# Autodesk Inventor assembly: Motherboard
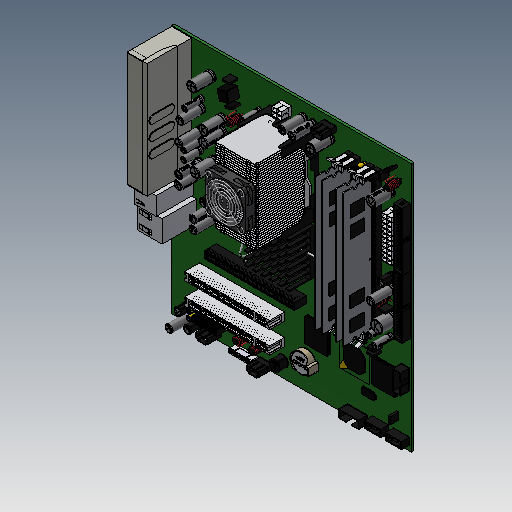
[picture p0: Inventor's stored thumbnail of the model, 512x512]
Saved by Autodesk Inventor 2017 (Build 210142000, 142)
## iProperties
Created: 2005-12
Part Number: Motherboard
Document SubType Name: Assembly
Designer: DanielSeverino
Author: DanielSeverino
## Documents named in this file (36)
- C:\Users\DanielSeverino\Desktop\01\Motherboard.iam
- C:\Users\DanielSeverino\Desktop\01\PCI Slot.ipt
- C:\Users\DanielSeverino\Desktop\01\Motherboard PCB.ipt
- C:\Users\DanielSeverino\Desktop\01\J9B1 Connector.ipt
- C:\Users\DanielSeverino\Desktop\01\J9C2 Connector.ipt
- C:\Users\DanielSeverino\Desktop\01\PCIE Connector.ipt
- C:\Users\DanielSeverino\Desktop\01\C9G5 connector.ipt
- C:\Users\DanielSeverino\Desktop\01\J9H2 Connector.ipt
- C:\Users\DanielSeverino\Desktop\01\IDE Male Connector.ipt
- C:\Users\DanielSeverino\Desktop\01\Power Supply Header 1.ipt
- C:\Users\DanielSeverino\Desktop\01\AGP slot.ipt
- C:\Users\DanielSeverino\Desktop\01\DDR Connector.ipt
- C:\Users\DanielSeverino\Desktop\01\Processor Heat Sink Mounting.ipt
- C:\Users\DanielSeverino\Desktop\01\Processor Heat Sink.ipt
- C:\Users\DanielSeverino\Desktop\01\RJ45 Module.ipt
- C:\Users\DanielSeverino\Desktop\01\USB Module.ipt
- C:\Users\DanielSeverino\Desktop\01\IO Interface Module.ipt
- C:\Users\DanielSeverino\Desktop\01\Capacitor 560 UF.ipt
- C:\Users\DanielSeverino\Desktop\01\Capacitor 1200 UF.ipt
- C:\Users\DanielSeverino\Desktop\01\Capacitor 640 UF.ipt
- C:\Users\DanielSeverino\Desktop\01\Capacitor 1000 UF.ipt
- C:\Users\DanielSeverino\Desktop\01\Capacitor 3000 UF.ipt
- C:\Users\DanielSeverino\Desktop\01\Choke.ipt
- C:\Users\DanielSeverino\Desktop\01\Battery.ipt
- C:\Users\DanielSeverino\Desktop\01\Bezel.ipt
- C:\Users\DanielSeverino\Desktop\01\Chip 15 x15.ipt
- C:\Users\DanielSeverino\Desktop\01\Capacitor 3500 UF.ipt
- C:\Users\DanielSeverino\Desktop\01\Chip block.ipt
- C:\Users\DanielSeverino\Desktop\01\Chip stand.ipt
- C:\Users\DanielSeverino\Desktop\01\Chip 13 x 6.ipt
- C:\Users\DanielSeverino\Desktop\01\Chip 22 x 11.ipt
- C:\Users\DanielSeverino\Desktop\01\Chip 24 x 23.ipt
- C:\Users\DanielSeverino\Desktop\01\RAM - DDR.ipt
- C:\Users\DanielSeverino\Desktop\01\Motherboard Heat Sink.ipt
- C:\Users\DanielSeverino\Desktop\01\Cooling Fan, 40mm x 40mm x 10 mm, 12VDC.iam
- C:\Users\DanielSeverino\Desktop\01\Power Supply Header 2.ipt
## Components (111 placed, 35 different names)
1. PCI Slot:3
2. Motherboard PCB:1
3. J9B1 Connector:1
4. J9B1 Connector:2
5. J9C2 Connector:1
6. PCIE Connector:1
7. C9G5 connector:1
8. J9H2 Connector:1
9. J9H2 Connector:2
10. C9G5 connector:2
11. IDE Male Connector:1
12. IDE Male Connector:2
13. Power Supply Header 1:1
14. J9B1 Connector:3
15. PCI Slot:1
16. PCI Slot:2
17. AGP slot:1
18. DDR Connector:1
19. DDR Connector:2
20. DDR Connector:3
21. DDR Connector:4
22. Processor Heat Sink Mounting:1
23. Processor Heat Sink:1
24. RJ45 Module:1
25. USB Module:1
26. IO Interface Module:1
27. Capacitor 560 UF:1
28. Capacitor 1200 UF:1
29. Capacitor 560 UF:2
30. Capacitor 640 UF:1
31. Capacitor 640 UF:2
32. Capacitor 1000 UF:2
33. Capacitor 3000 UF:1
34. Capacitor 1200 UF:2
35. Capacitor 560 UF:8
36. Capacitor 560 UF:9
37. Capacitor 560 UF:10
38. Capacitor 560 UF:11
39. Capacitor 560 UF:12
40. Capacitor 3000 UF:2
41. Capacitor 3000 UF:3
42. Capacitor 3000 UF:4
43. Capacitor 3000 UF:5
44. Capacitor 560 UF:13
45. Capacitor 560 UF:14
46. Capacitor 1200 UF:3
47. Capacitor 1200 UF:4
48. Capacitor 1200 UF:5
49. Capacitor 640 UF:8
50. Capacitor 640 UF:9
51. Capacitor 640 UF:10
52. Capacitor 640 UF:11
53. Capacitor 640 UF:12
54. Capacitor 640 UF:13
55. Capacitor 3000 UF:6
56. Capacitor 560 UF:16
57. Capacitor 1200 UF:6
58. Capacitor 1200 UF:7
59. Capacitor 1200 UF:8
60. Capacitor 3000 UF:7
61. Choke:1
62. Choke:2
63. Choke:3
64. Battery:1
65. Bezel:1
66. Chip 15 x15:1
67. Capacitor 3500 UF:1
68. Capacitor 1000 UF:5
69. Capacitor 1000 UF:6
70. Capacitor 1200 UF:9
71. Capacitor 1200 UF:11
72. Capacitor 1200 UF:10
73. Capacitor 1200 UF:12
74. Capacitor 1000 UF:7
75. Capacitor 1000 UF:8
76. Capacitor 1000 UF:9
77. Chip block:1
78. Chip block:2
79. Chip block:3
80. Chip stand:1
81. Chip stand:2
82. Chip stand:3
83. Chip stand:4
84. Chip stand:5
85. Chip stand:6
86. Chip stand:7
87. Chip stand:8
88. Chip stand:9
89. Chip stand:10
90. Chip stand:11
91. Chip stand:12
92. Chip stand:13
93. Chip 13 x 6:1
94. Chip 13 x 6:2
95. Chip 13 x 6:3
96. Chip 22 x 11:1
97. Chip 22 x 11:3
98. Chip 24 x 23:1
99. Chip 24 x 23:2
100. Choke:4
101. Choke:5
102. Choke:6
103. Choke:7
104. Capacitor 560 UF:17
105. RAM - DDR:1
106. RAM - DDR:2
107. RAM - DDR:3
108. RAM - DDR:4
109. Motherboard Heat Sink:1
110. Cooling Fan, 40mm x 40mm x 10 mm, 12VDC:1 [sub-assembly]
111. Power Supply Header 2:1
